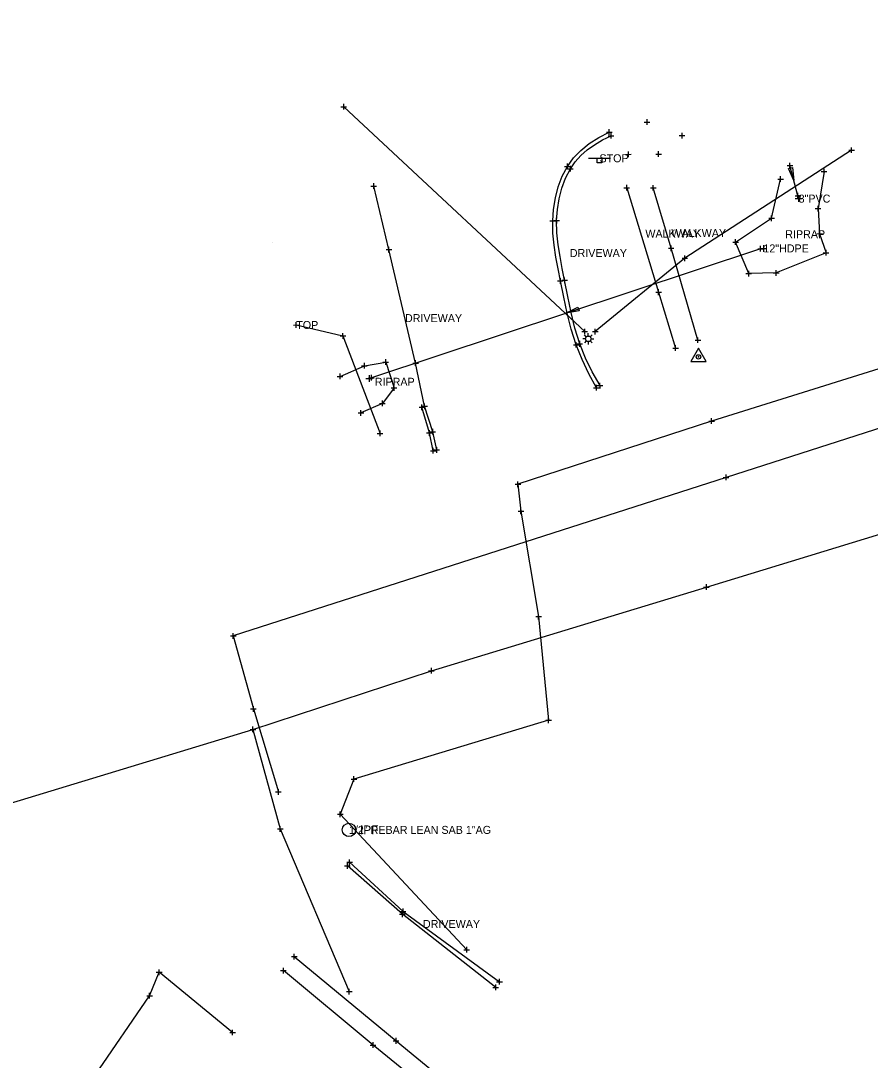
# Model space of a CAD drawing. Extents: x 1729655 to 1739338, y 463812 to 469501.
# Drawn here: x 1736096.3 to 1736287.2, y 467112.2 to 467346 of the extents above; entities that cross this region are included whole.
import ezdxf

# ---------------------------------------------------------------- set-up
doc = ezdxf.new("R2010")
doc.units = 0
for name, color, linetype in [('Default', 7, 'Continuous'), ('S_Bridge_Column_Round', 7, 'Continuous'), ('S_Bridge_Curb', 7, 'Continuous'), ('S_Bridge_Deck', 7, 'Continuous'), ('S_Bridge_ExpansionJoint', 7, 'Continuous'), ('S_Control_Temp_Traverse', 7, 'Continuous'), ('S_Ground_SpotElevation', 7, 'Continuous'), ('S_Guardrail_Beam', 7, 'Continuous'), ('S_Property_ConcPad', 7, 'Continuous'), ('S_Property_Garden', 7, 'Continuous'), ('S_Property_Walkways', 7, 'Continuous'), ('S_RetWall_Top', 7, 'Continuous'), ('S_Roadway_Drive_Gravel', 7, 'Continuous'), ('S_Survey_Shot', 7, 'Continuous'), ('S_Terrain_Breaklines', 7, 'Continuous'), ('S_Terrain_High_Points', 7, 'Continuous'), ('S_Terrain_Holes', 7, 'Continuous'), ('S_Utilities_Hydrant', 7, 'Continuous'), ('S_Utilities_Pole_StreetLight', 7, 'Continuous'), ('S_Utilities_UG_Water_Gate', 7, 'Continuous')]:
    doc.layers.add(name, color=color, linetype=linetype)

msp = doc.modelspace()

# ---------------------------------------------------------------- linework, layer by layer
at = {"layer": 'Default'}
for p, q in [((1736271.12, 467305.98), (1736271.12, 467305.98)), ((1736152.94, 467296.04), (1736152.94, 467296.04)), ((1736263.2, 467294.78), (1736263.2, 467294.78)), ((1736174.58, 467265.54), (1736174.58, 467265.54))]:
    msp.add_line(p, q, dxfattribs=at)
at = {"layer": 'S_Bridge_Column_Round'}
for p, q in [((1736168.25, 467326.63), (1736169.52, 467326.64)), ((1736168.88, 467326), (1736168.88, 467327.27)), ((1736168.88, 467326.64), (1736168.88, 467326.64)), ((1736237.08, 467322.56), (1736237.07, 467323.83)), ((1736237.08, 467322.56), (1736237.07, 467323.83)), ((1736228.55, 467320.32), (1736228.55, 467321.6)), ((1736236.44, 467323.19), (1736237.71, 467323.2)), ((1736236.44, 467323.19), (1736237.71, 467323.2)), ((1736237.07, 467323.19), (1736237.07, 467323.19)), ((1736237.07, 467323.19), (1736237.07, 467323.19)), ((1736227.91, 467320.96), (1736229.18, 467320.96)), ((1736228.32, 467320.13), (1736229.59, 467320.13)), ((1736228.55, 467320.96), (1736228.55, 467320.96)), ((1736228.96, 467319.49), (1736228.96, 467320.76)), ((1736228.96, 467320.13), (1736228.96, 467320.13)), ((1736244.27, 467320.14), (1736245.54, 467320.14)), ((1736244.91, 467319.51), (1736244.91, 467320.78)), ((1736244.91, 467320.14), (1736244.91, 467320.14)), ((1736232.85, 467315.3), (1736232.85, 467316.57)), ((1736239.66, 467315.36), (1736239.65, 467316.63)), ((1736282.4, 467316.87), (1736283.68, 467316.87)), ((1736283.04, 467316.24), (1736283.04, 467317.51)), ((1736283.04, 467316.87), (1736283.04, 467316.87)), ((1736232.22, 467315.93), (1736233.49, 467315.94)), ((1736232.85, 467315.93), (1736232.85, 467315.93)), ((1736239.02, 467315.99), (1736240.29, 467315.99)), ((1736239.65, 467315.99), (1736239.65, 467315.99)), ((1736218.53, 467313.21), (1736219.81, 467313.21)), ((1736219.17, 467312.57), (1736219.17, 467313.85)), ((1736219.17, 467313.21), (1736219.17, 467313.21)), ((1736219.2, 467312.7), (1736220.47, 467312.7)), ((1736219.83, 467312.07), (1736219.83, 467313.34)), ((1736219.83, 467312.7), (1736219.83, 467312.7)), ((1736268.52, 467313.41), (1736269.79, 467313.41)), ((1736269.16, 467312.77), (1736269.16, 467314.05)), ((1736269.16, 467313.41), (1736269.16, 467313.41)), ((1736276.21, 467312.07), (1736277.48, 467312.07)), ((1736276.85, 467311.44), (1736276.84, 467312.71)), ((1736276.84, 467312.07), (1736276.84, 467312.07)), ((1736266.44, 467310.37), (1736267.72, 467310.37)), ((1736267.08, 467309.73), (1736267.08, 467311.01)), ((1736267.08, 467310.37), (1736267.08, 467310.37)), ((1736175, 467308.79), (1736176.27, 467308.8)), ((1736175.63, 467308.16), (1736175.63, 467309.43)), ((1736175.63, 467308.79), (1736175.63, 467308.79)), ((1736231.87, 467308.42), (1736233.14, 467308.43)), ((1736232.5, 467307.79), (1736232.5, 467309.06)), ((1736232.5, 467308.43), (1736232.5, 467308.43)), ((1736237.8, 467308.41), (1736239.08, 467308.41)), ((1736238.44, 467307.77), (1736238.44, 467309.04)), ((1736238.44, 467308.41), (1736238.44, 467308.41)), ((1736270.96, 467306), (1736270.96, 467307.27)), ((1736270.32, 467306.63), (1736271.59, 467306.63)), ((1736270.96, 467306.63), (1736270.96, 467306.63)), ((1736274.86, 467303.73), (1736276.14, 467303.74)), ((1736275.5, 467303.1), (1736275.5, 467304.37)), ((1736275.5, 467303.73), (1736275.5, 467303.73)), ((1736215.22, 467300.97), (1736216.5, 467300.97)), ((1736215.86, 467300.33), (1736215.86, 467301.61)), ((1736215.86, 467300.97), (1736215.86, 467300.97)), ((1736216.1, 467301.04), (1736217.37, 467301.04)), ((1736216.74, 467300.41), (1736216.73, 467301.68)), ((1736216.73, 467301.04), (1736216.73, 467301.04)), ((1736264.4, 467301.57), (1736265.67, 467301.58)), ((1736265.03, 467300.94), (1736265.03, 467302.21)), ((1736265.03, 467301.57), (1736265.03, 467301.57)), ((1736275.2, 467298.09), (1736276.47, 467298.1)), ((1736275.2, 467298.09), (1736276.47, 467298.1)), ((1736275.84, 467297.46), (1736275.84, 467298.73)), ((1736275.84, 467297.46), (1736275.84, 467298.73)), ((1736275.84, 467298.09), (1736275.84, 467298.09)), ((1736275.84, 467298.09), (1736275.84, 467298.09)), ((1736256.32, 467296.21), (1736257.59, 467296.21)), ((1736256.96, 467295.58), (1736256.96, 467296.85)), ((1736256.96, 467296.21), (1736256.96, 467296.21)), ((1736178.41, 467294.52), (1736179.69, 467294.52)), ((1736179.05, 467293.88), (1736179.05, 467295.16)), ((1736179.05, 467294.52), (1736179.05, 467294.52)), ((1736241.84, 467294.82), (1736243.11, 467294.82)), ((1736242.47, 467294.19), (1736242.47, 467295.46)), ((1736242.47, 467294.82), (1736242.47, 467294.82)), ((1736245.55, 467291.94), (1736245.54, 467293.21)), ((1736261.92, 467294.71), (1736263.2, 467294.71)), ((1736262.56, 467294.07), (1736262.56, 467295.35)), ((1736262.56, 467294.71), (1736262.56, 467294.71)), ((1736276.66, 467293.8), (1736277.93, 467293.81)), ((1736277.3, 467293.17), (1736277.29, 467294.44)), ((1736277.29, 467293.81), (1736277.29, 467293.81)), ((1736244.91, 467292.57), (1736246.18, 467292.57)), ((1736245.54, 467292.57), (1736245.54, 467292.57)), ((1736259.28, 467289.13), (1736260.55, 467289.14)), ((1736259.91, 467288.5), (1736259.91, 467289.77)), ((1736259.91, 467289.13), (1736259.91, 467289.13)), ((1736265.44, 467289.24), (1736266.72, 467289.25)), ((1736266.08, 467288.61), (1736266.08, 467289.88)), ((1736266.08, 467289.25), (1736266.08, 467289.25)), ((1736216.95, 467287.48), (1736218.23, 467287.49)), ((1736217.59, 467286.85), (1736217.59, 467288.12)), ((1736217.59, 467287.48), (1736217.59, 467287.48)), ((1736217.9, 467287.62), (1736219.17, 467287.62)), ((1736218.54, 467286.99), (1736218.53, 467288.26)), ((1736218.53, 467287.62), (1736218.53, 467287.62)), ((1736239.01, 467284.94), (1736240.28, 467284.94)), ((1736239.65, 467284.3), (1736239.64, 467285.58)), ((1736239.64, 467284.94), (1736239.64, 467284.94)), ((1736157.57, 467277.55), (1736158.84, 467277.56)), ((1736158.2, 467276.92), (1736158.2, 467278.19)), ((1736158.2, 467277.56), (1736158.2, 467277.56)), ((1736168.08, 467275.1), (1736169.35, 467275.1)), ((1736168.72, 467274.46), (1736168.71, 467275.74)), ((1736168.71, 467275.1), (1736168.71, 467275.1)), ((1736222.41, 467276.09), (1736223.68, 467276.09)), ((1736223.05, 467275.46), (1736223.05, 467276.73)), ((1736223.05, 467276.09), (1736223.05, 467276.09)), ((1736224.76, 467276.08), (1736226.03, 467276.08)), ((1736225.4, 467275.44), (1736225.4, 467276.71)), ((1736225.4, 467276.08), (1736225.4, 467276.08)), ((1736248.49, 467273.51), (1736248.49, 467274.78)), ((1736220.5, 467273.09), (1736221.78, 467273.1)), ((1736221.14, 467272.46), (1736221.14, 467273.73)), ((1736221.14, 467273.09), (1736221.14, 467273.09)), ((1736221.3, 467273.32), (1736222.57, 467273.32)), ((1736221.94, 467272.68), (1736221.93, 467273.96)), ((1736221.94, 467273.32), (1736221.94, 467273.32)), ((1736242.82, 467272.35), (1736244.09, 467272.36)), ((1736243.45, 467271.72), (1736243.45, 467272.99)), ((1736243.45, 467272.36), (1736243.45, 467272.36)), ((1736247.85, 467274.14), (1736249.13, 467274.14)), ((1736248.49, 467274.14), (1736248.49, 467274.14)), ((1736178.33, 467268.59), (1736178.33, 467269.87)), ((1736172.88, 467268.38), (1736174.16, 467268.38)), ((1736173.52, 467267.74), (1736173.52, 467269.02)), ((1736173.52, 467268.38), (1736173.52, 467268.38)), ((1736177.69, 467269.23), (1736178.97, 467269.23)), ((1736178.33, 467269.23), (1736178.33, 467269.23)), ((1736184.38, 467269), (1736185.65, 467269)), ((1736185.02, 467268.36), (1736185.02, 467269.64)), ((1736185.02, 467269), (1736185.02, 467269)), ((1736167.4, 467266), (1736168.68, 467266)), ((1736168.04, 467265.36), (1736168.04, 467266.64)), ((1736168.04, 467266), (1736168.04, 467266)), ((1736174.46, 467265.69), (1736175.74, 467265.69)), ((1736175.1, 467265.05), (1736175.1, 467266.33)), ((1736175.1, 467265.69), (1736175.1, 467265.69)), ((1736179.54, 467263.41), (1736180.81, 467263.42)), ((1736180.18, 467262.78), (1736180.17, 467264.05)), ((1736180.18, 467263.41), (1736180.18, 467263.41)), ((1736225.04, 467263.44), (1736226.32, 467263.44)), ((1736225.04, 467263.44), (1736226.32, 467263.44)), ((1736225.68, 467262.8), (1736225.68, 467264.07)), ((1736225.68, 467262.8), (1736225.68, 467264.07)), ((1736225.68, 467263.44), (1736225.68, 467263.44)), ((1736225.68, 467263.44), (1736225.68, 467263.44)), ((1736225.84, 467263.94), (1736227.11, 467263.95)), ((1736225.84, 467263.94), (1736227.11, 467263.95)), ((1736226.48, 467263.31), (1736226.47, 467264.58)), ((1736226.48, 467263.31), (1736226.47, 467264.58)), ((1736226.48, 467263.95), (1736226.48, 467263.95)), ((1736226.48, 467263.95), (1736226.48, 467263.95)), ((1736177.58, 467259.29), (1736177.58, 467260.56)), ((1736172.75, 467257.14), (1736172.75, 467258.42)), ((1736176.94, 467259.93), (1736178.22, 467259.93)), ((1736177.58, 467259.93), (1736177.58, 467259.93)), ((1736185.8, 467259.04), (1736187.07, 467259.04)), ((1736186.43, 467259.28), (1736187.7, 467259.28)), ((1736186.44, 467258.4), (1736186.44, 467259.68)), ((1736186.44, 467259.04), (1736186.44, 467259.04)), ((1736187.07, 467258.64), (1736187.06, 467259.92)), ((1736187.06, 467259.28), (1736187.06, 467259.28)), ((1736172.11, 467257.78), (1736173.38, 467257.78)), ((1736172.75, 467257.78), (1736172.75, 467257.78)), ((1736250.92, 467255.93), (1736252.19, 467255.93)), ((1736251.56, 467255.3), (1736251.55, 467256.57)), ((1736251.55, 467255.93), (1736251.55, 467255.93)), ((1736177.04, 467252.52), (1736177.03, 467253.8)), ((1736188.14, 467252.63), (1736188.13, 467253.9)), ((1736188.23, 467253.53), (1736189.5, 467253.53)), ((1736188.87, 467252.9), (1736188.87, 467254.17)), ((1736188.87, 467253.53), (1736188.87, 467253.53)), ((1736176.4, 467253.16), (1736177.67, 467253.16)), ((1736177.03, 467253.16), (1736177.03, 467253.16)), ((1736187.5, 467253.27), (1736188.77, 467253.27)), ((1736188.13, 467253.27), (1736188.13, 467253.27)), ((1736188.36, 467249.29), (1736189.63, 467249.29)), ((1736189, 467248.66), (1736189, 467249.93)), ((1736189, 467249.29), (1736189, 467249.29)), ((1736189.15, 467249.45), (1736190.42, 467249.46)), ((1736189.79, 467248.82), (1736189.79, 467250.09)), ((1736189.79, 467249.45), (1736189.79, 467249.45)), ((1736207.4, 467241.74), (1736208.67, 467241.74)), ((1736208.04, 467241.1), (1736208.04, 467242.38)), ((1736208.04, 467241.74), (1736208.04, 467241.74)), ((1736254.18, 467243.26), (1736255.45, 467243.26)), ((1736254.82, 467242.62), (1736254.82, 467243.9)), ((1736254.82, 467243.26), (1736254.82, 467243.26)), ((1736208.08, 467235.68), (1736209.35, 467235.68)), ((1736208.71, 467235.04), (1736208.71, 467236.32)), ((1736208.71, 467235.68), (1736208.71, 467235.68)), ((1736249.77, 467218.6), (1736251.04, 467218.61)), ((1736250.41, 467217.97), (1736250.4, 467219.24)), ((1736250.41, 467218.61), (1736250.41, 467218.61)), ((1736212.06, 467211.98), (1736213.33, 467211.99)), ((1736212.69, 467211.35), (1736212.69, 467212.62)), ((1736212.69, 467211.99), (1736212.69, 467211.99)), ((1736143.41, 467207.62), (1736144.68, 467207.63)), ((1736144.05, 467206.99), (1736144.05, 467208.26)), ((1736144.05, 467207.62), (1736144.05, 467207.62)), ((1736187.94, 467199.8), (1736189.21, 467199.8)), ((1736188.58, 467199.16), (1736188.57, 467200.43)), ((1736188.58, 467199.8), (1736188.58, 467199.8)), ((1736147.94, 467191.2), (1736149.21, 467191.21)), ((1736148.58, 467190.57), (1736148.57, 467191.84)), ((1736148.57, 467191.2), (1736148.57, 467191.2)), ((1736214.28, 467188.66), (1736215.55, 467188.67)), ((1736214.91, 467188.03), (1736214.91, 467189.3)), ((1736214.91, 467188.67), (1736214.91, 467188.67)), ((1736147.83, 467186.59), (1736149.1, 467186.6)), ((1736147.83, 467186.59), (1736149.1, 467186.6)), ((1736148.47, 467185.96), (1736148.46, 467187.23)), ((1736148.47, 467185.96), (1736148.46, 467187.23)), ((1736148.46, 467186.6), (1736148.46, 467186.6)), ((1736148.46, 467186.6), (1736148.46, 467186.6)), ((1736170.52, 467175.43), (1736171.79, 467175.43)), ((1736171.16, 467174.79), (1736171.15, 467176.06)), ((1736171.16, 467175.43), (1736171.16, 467175.43)), ((1736153.56, 467172.56), (1736154.83, 467172.56)), ((1736154.2, 467171.92), (1736154.2, 467173.19)), ((1736154.2, 467172.56), (1736154.2, 467172.56)), ((1736167.46, 467167.52), (1736168.73, 467167.52)), ((1736168.09, 467166.88), (1736168.09, 467168.16)), ((1736168.09, 467167.52), (1736168.09, 467167.52)), ((1736154.6, 467163.6), (1736154.6, 467164.87)), ((1736153.96, 467164.23), (1736155.24, 467164.23)), ((1736154.6, 467164.23), (1736154.6, 467164.23)), ((1736169.05, 467155.91), (1736170.33, 467155.91)), ((1736169.55, 467156.71), (1736170.82, 467156.71)), ((1736169.69, 467155.27), (1736169.69, 467156.54)), ((1736169.69, 467155.91), (1736169.69, 467155.91)), ((1736170.19, 467156.07), (1736170.19, 467157.35)), ((1736170.19, 467156.71), (1736170.19, 467156.71)), ((1736182.23, 467145.02), (1736182.23, 467146.3)), ((1736181.42, 467145.02), (1736182.69, 467145.02)), ((1736181.59, 467145.66), (1736182.87, 467145.66)), ((1736182.06, 467144.38), (1736182.05, 467145.65)), ((1736182.05, 467145.02), (1736182.05, 467145.02)), ((1736182.23, 467145.66), (1736182.23, 467145.66)), ((1736195.89, 467137.06), (1736197.17, 467137.06)), ((1736196.53, 467136.42), (1736196.53, 467137.69)), ((1736196.53, 467137.06), (1736196.53, 467137.06)), ((1736157.11, 467135.5), (1736158.38, 467135.5)), ((1736157.74, 467134.87), (1736157.74, 467136.14)), ((1736157.74, 467135.5), (1736157.74, 467135.5)), ((1736126.75, 467131.97), (1736128.03, 467131.97)), ((1736126.75, 467131.97), (1736128.03, 467131.97)), ((1736127.39, 467131.34), (1736127.39, 467132.61)), ((1736127.39, 467131.34), (1736127.39, 467132.61)), ((1736127.39, 467131.97), (1736127.39, 467131.97)), ((1736127.39, 467131.97), (1736127.39, 467131.97)), ((1736154.67, 467132.37), (1736155.95, 467132.37)), ((1736155.31, 467131.73), (1736155.31, 467133)), ((1736155.31, 467132.37), (1736155.31, 467132.37)), ((1736203.25, 467129.84), (1736204.53, 467129.85)), ((1736203.89, 467129.21), (1736203.89, 467130.48)), ((1736203.89, 467129.84), (1736203.89, 467129.84)), ((1736125.25, 467126.08), (1736125.25, 467127.35)), ((1736169.49, 467127.65), (1736170.76, 467127.65)), ((1736170.13, 467127.01), (1736170.13, 467128.28)), ((1736170.13, 467127.65), (1736170.13, 467127.65)), ((1736202.41, 467128.57), (1736203.68, 467128.58)), ((1736203.05, 467127.94), (1736203.04, 467129.21)), ((1736203.04, 467128.58), (1736203.04, 467128.58)), ((1736124.61, 467126.71), (1736125.89, 467126.71)), ((1736125.25, 467126.71), (1736125.25, 467126.71)), ((1736143.27, 467118.43), (1736144.55, 467118.44)), ((1736143.91, 467117.8), (1736143.91, 467119.07)), ((1736143.91, 467118.43), (1736143.91, 467118.43)), ((1736174.84, 467115.59), (1736176.12, 467115.6)), ((1736175.48, 467114.96), (1736175.48, 467116.23)), ((1736175.48, 467115.59), (1736175.48, 467115.59)), ((1736180, 467116.56), (1736181.27, 467116.56)), ((1736180.63, 467115.92), (1736180.63, 467117.2)), ((1736180.63, 467116.56), (1736180.63, 467116.56))]:
    msp.add_line(p, q, dxfattribs=at)
at = {"layer": 'S_Bridge_Curb'}
msp.add_line((1736223.87, 467315.05), (1736228.86, 467315.05), dxfattribs=at)
msp.add_lwpolyline([(1736225.86, 467315.05), (1736226.86, 467315.05), (1736226.86, 467314.05), (1736225.86, 467314.05)], close=True, dxfattribs=at)
at = {"layer": 'S_Bridge_Deck'}
for p, q in [((1736223.21, 467274.45), (1736222.59, 467274.45)), ((1736223.4, 467274.89), (1736222.96, 467275.33)), ((1736223.84, 467275.07), (1736223.84, 467275.7)), ((1736224.28, 467274.89), (1736224.72, 467275.33)), ((1736224.46, 467274.45), (1736225.09, 467274.45)), ((1736223.4, 467274.01), (1736222.96, 467273.57)), ((1736223.84, 467273.83), (1736223.84, 467273.2)), ((1736224.28, 467274.01), (1736224.72, 467273.57))]:
    msp.add_line(p, q, dxfattribs=at)
msp.add_circle((1736223.84, 467274.45), 0.624, dxfattribs=at)
at = {"layer": 'S_Bridge_ExpansionJoint'}
for p, q in [((1736270.37, 467305.98), (1736271.87, 467305.98)), ((1736271.12, 467306.73), (1736271.12, 467305.23)), ((1736263.2, 467295.53), (1736263.2, 467294.03)), ((1736262.45, 467294.78), (1736263.95, 467294.78)), ((1736173.83, 467265.54), (1736175.33, 467265.54)), ((1736174.58, 467266.29), (1736174.58, 467264.79))]:
    msp.add_line(p, q, dxfattribs=at)
at = {"layer": 'S_Control_Temp_Traverse'}
for p, q in [((1736248.49, 467270.38), (1736248.74, 467270.38)), ((1736248.61, 467270.51), (1736248.61, 467270.26))]:
    msp.add_line(p, q, dxfattribs=at)
msp.add_lwpolyline([(1736246.88, 467269.38), (1736250.34, 467269.38), (1736248.61, 467272.38)], close=True, dxfattribs=at)
msp.add_circle((1736248.61, 467270.38), 0.499, dxfattribs=at)
at = {"layer": 'S_Ground_SpotElevation'}
for p, q in [((1736125.25, 467126.71), (1736127.39, 467131.97)), ((1736113.03, 467108.81), (1736125.25, 467126.71))]:
    msp.add_line(p, q, dxfattribs=at)
for points in [[(1736225.68, 467263.44), (1736223.97, 467266.59), (1736222.45, 467269.8), (1736221.14, 467273.09), (1736220.03, 467276.61), (1736219.11, 467280.2), (1736218.33, 467283.84), (1736217.59, 467287.48), (1736217.05, 467290.16), (1736216.56, 467292.83), (1736216.16, 467295.52), (1736215.91, 467298.23), (1736215.86, 467300.97), (1736216.04, 467303.56), (1736216.44, 467306.13), (1736217.1, 467308.63), (1736218, 467311.01), (1736219.17, 467313.21), (1736220.55, 467315.12), (1736222.18, 467316.83), (1736224.06, 467318.36), (1736226.18, 467319.73), (1736228.55, 467320.96)], [(1736189.79, 467249.45), (1736188.87, 467253.53), (1736187.06, 467259.28), (1736185.02, 467269), (1736179.05, 467294.52), (1736175.63, 467308.79)], [(1736170.19, 467156.71), (1736182.23, 467145.66), (1736203.89, 467129.84)]]:
    msp.add_lwpolyline(points, dxfattribs=at)
at = {"layer": 'S_Guardrail_Beam'}
for points in [[(1736226.48, 467263.95), (1736224.75, 467267), (1736223.23, 467270.12), (1736221.94, 467273.32), (1736220.85, 467276.81), (1736219.98, 467280.38), (1736219.24, 467284), (1736218.53, 467287.62), (1736218, 467290.28), (1736217.49, 467292.94), (1736217.07, 467295.62), (1736216.8, 467298.31), (1736216.73, 467301.04), (1736216.89, 467303.51), (1736217.27, 467305.96), (1736217.87, 467308.34), (1736218.73, 467310.61), (1736219.83, 467312.7), (1736220.93, 467314.25), (1736222.19, 467315.66), (1736223.63, 467316.95), (1736225.24, 467318.11), (1736227.02, 467319.17), (1736228.96, 467320.13)], [(1736189, 467249.29), (1736188.13, 467253.27), (1736186.44, 467259.04)]]:
    msp.add_lwpolyline(points, dxfattribs=at)
at = {"layer": 'S_Property_ConcPad'}
msp.add_lwpolyline([(1736158.2, 467277.56), (1736168.71, 467275.1), (1736177.03, 467253.16)], dxfattribs=at)
at = {"layer": 'S_Property_Garden'}
for p, q in [((1736232.5, 467308.43), (1736239.64, 467284.94)), ((1736242.47, 467294.82), (1736238.44, 467308.41)), ((1736248.49, 467274.14), (1736242.47, 467294.82)), ((1736239.64, 467284.94), (1736243.45, 467272.36))]:
    msp.add_line(p, q, dxfattribs=at)
at = {"layer": 'S_Property_Walkways'}
for points in [[(1736276.84, 467312.07), (1736275.5, 467303.73), (1736275.84, 467298.09), (1736277.29, 467293.81), (1736266.08, 467289.25), (1736259.91, 467289.13), (1736256.96, 467296.21), (1736265.03, 467301.57), (1736267.08, 467310.37)], [(1736168.04, 467266), (1736173.52, 467268.38), (1736178.33, 467269.23), (1736180.18, 467263.41), (1736177.58, 467259.93), (1736172.75, 467257.78)]]:
    msp.add_lwpolyline(points, dxfattribs=at)
at = {"layer": 'S_RetWall_Top'}
msp.add_line((1736262.56, 467294.71), (1736175.1, 467265.69), dxfattribs=at)
for points in [[(1736270.96, 467306.63), (1736269.16, 467313.41)], [(1736262.56, 467294.71), (1736175.1, 467265.69)]]:
    msp.add_lwpolyline(points, dxfattribs=at)
at = {"layer": 'S_Roadway_Drive_Gravel'}
for points in [[(1736203.04, 467128.58), (1736182.05, 467145.02), (1736169.69, 467155.91)], [(1736157.74, 467135.5), (1736180.63, 467116.56), (1736203.92, 467097.44)], [(1736143.91, 467118.43), (1736127.39, 467131.97)], [(1736201.36, 467094.5), (1736175.48, 467115.59), (1736155.31, 467132.37)]]:
    msp.add_lwpolyline(points, dxfattribs=at)
at = {"layer": 'S_Survey_Shot'}
for points in [[(1735327.94, 466925.11), (1735706.87, 467043.8), (1735777.22, 467067.85), (1735856.5, 467093.65), (1735947.31, 467123.71), (1736072.24, 467163.39), (1736148.46, 467186.6), (1736188.58, 467199.8), (1736250.41, 467218.61), (1736341.55, 467246.49), (1736425.62, 467273.68), (1736484.8, 467292.24), (1736522.29, 467304.69), (1736527.82, 467289.35)], [(1736148.46, 467186.6), (1736154.6, 467164.23), (1736170.13, 467127.65)]]:
    msp.add_lwpolyline(points, dxfattribs=at)
at = {"layer": 'S_Terrain_Breaklines'}
for p, q in [((1736270.06, 467310.02), (1736270.06, 467310.02)), ((1736218.83, 467280.2), (1736218.83, 467280.2))]:
    msp.add_line(p, q, dxfattribs=at)
for points in [[(1736270.06, 467310.02), (1736268.87, 467312.77), (1736269.73, 467313)], [(1736218.83, 467280.2), (1736221.51, 467281.56), (1736221.79, 467280.71)]]:
    msp.add_lwpolyline(points, close=True, dxfattribs=at)
at = {"layer": 'S_Terrain_Holes'}
msp.add_circle((1736170.05, 467164), 1.5, dxfattribs=at)
at = {"layer": 'S_Utilities_Hydrant'}
msp.add_lwpolyline([(1736552.39, 467339.15), (1736497.56, 467321.77), (1736438.65, 467302.12), (1736346.71, 467272.76), (1736254.82, 467243.26), (1736144.05, 467207.62), (1736148.57, 467191.2), (1736154.2, 467172.56)], dxfattribs=at)
at = {"layer": 'S_Utilities_Pole_StreetLight'}
for points in [[(1736223.05, 467276.09), (1736168.88, 467326.64)], [(1736283.04, 467316.87), (1736245.54, 467292.57), (1736225.4, 467276.08)]]:
    msp.add_lwpolyline(points, dxfattribs=at)
at = {"layer": 'S_Utilities_UG_Water_Gate'}
msp.add_lwpolyline([(1736536.81, 467345.97), (1736495.47, 467332.79), (1736483.38, 467325.19), (1736438.45, 467310.99), (1736425.99, 467310.48), (1736340.18, 467283.67), (1736251.55, 467255.93), (1736208.04, 467241.74), (1736208.71, 467235.68), (1736212.69, 467211.99), (1736214.91, 467188.67), (1736171.16, 467175.43), (1736168.09, 467167.52), (1736196.53, 467137.06)], dxfattribs=at)

# ---------------------------------------------------------------- texts
at = {"layer": 'S_Terrain_High_Points'}
for s, p in [('STOP', (1736226.36, 467314.15)), ('8"PVC', (1736271.12, 467305.08)), ('WALKWAY', (1736236.67, 467297.2)), ('WALKWAY', (1736242.51, 467297.34)), ('RIPRAP', (1736268.12, 467297.07)), ('12"HDPE', (1736263.2, 467293.88)), ('DRIVEWAY', (1736219.69, 467292.84)), ('DRIVEWAY', (1736182.64, 467278.2)), ('TOP', (1736158.2, 467276.66)), ('RIPRAP', (1736175.86, 467263.88)), ('1/2" REBAR LEAN SAB 1"AG', (1736170.05, 467163.1)), ('DRIVEWAY', (1736186.68, 467141.94))]:
    msp.add_text(s, height=1.8, dxfattribs=at).set_placement(p)
at = {"layer": 'S_Terrain_Holes'}
msp.add_text('IPF', height=1.996, dxfattribs=at).set_placement((1736172.54, 467163))

doc.saveas('drawing.dxf')
